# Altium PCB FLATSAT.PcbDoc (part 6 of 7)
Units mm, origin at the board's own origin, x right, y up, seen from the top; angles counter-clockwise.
Board outline 430 x 350 mm, 5 copper layers (Top Layer, Internal Plane 1, Internal Plane 2, DELETEME, Bottom Layer); 808 components, 852 nets, 6407 pads, 939 vias.
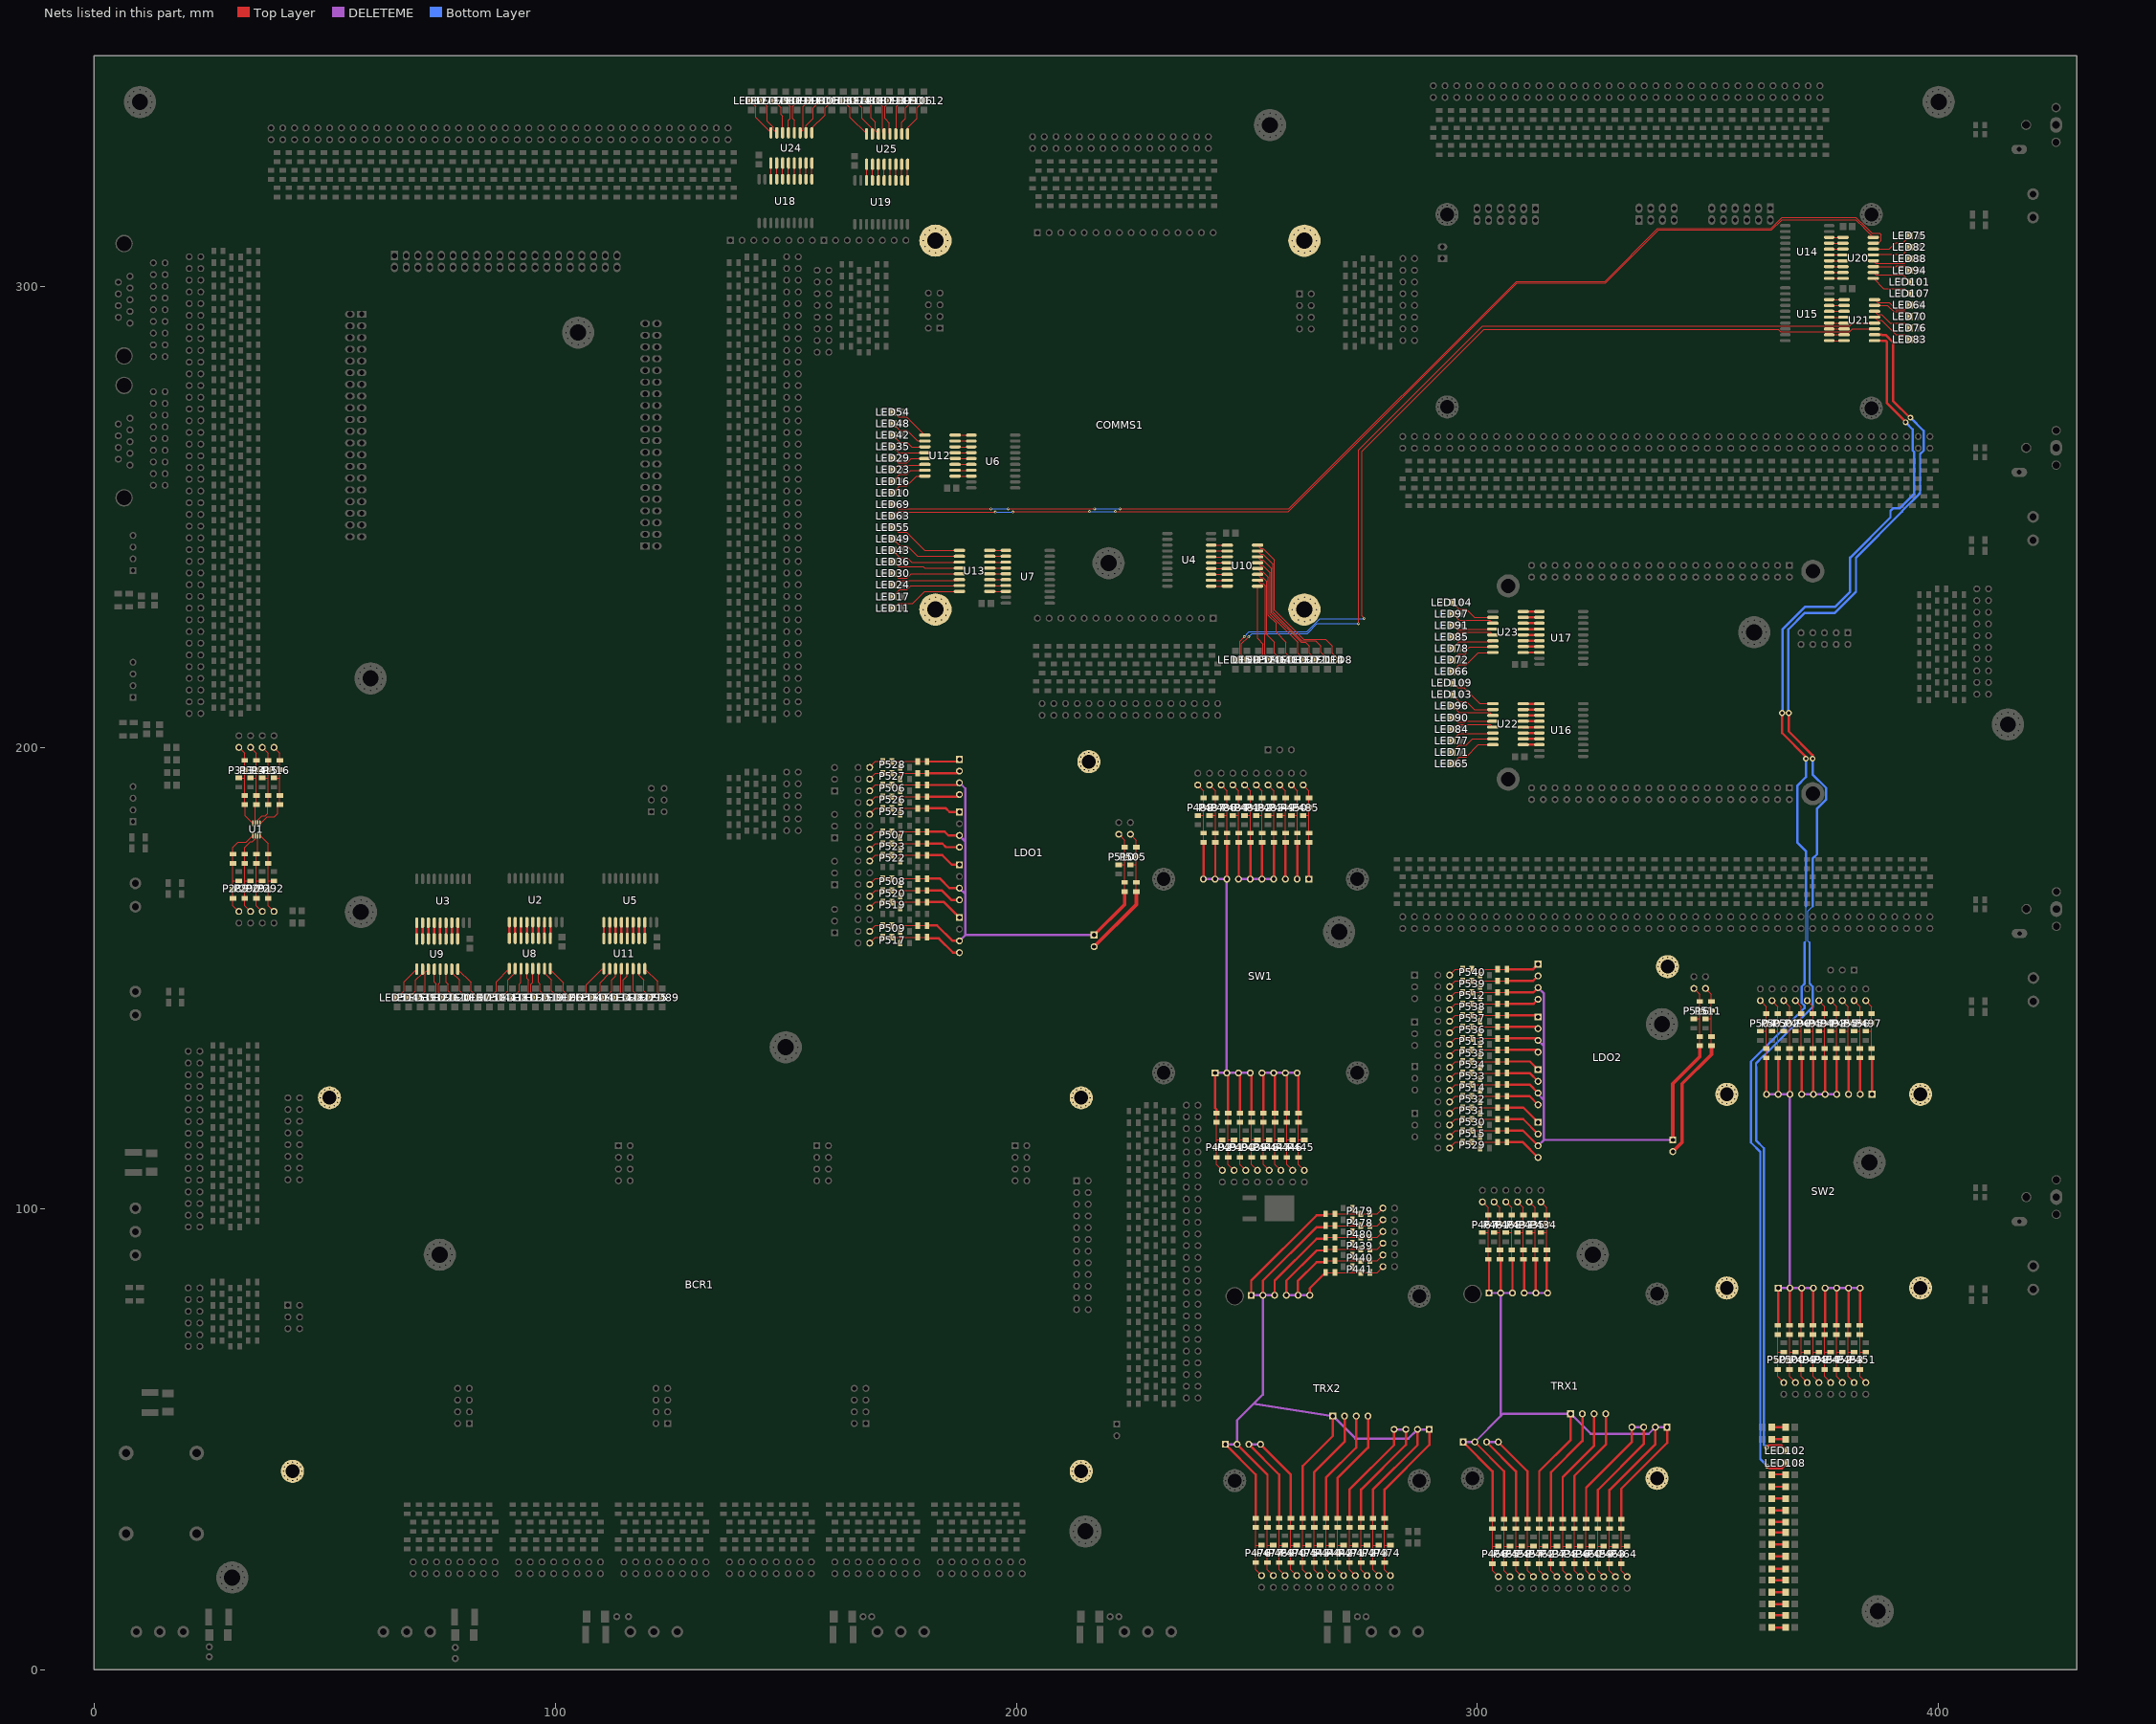
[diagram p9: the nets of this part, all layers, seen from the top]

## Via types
v1: diameter 1.016, hole 0.508, Top Layer to Bottom Layer, 541 vias
v2: diameter 0.6, hole 0.3, Top Layer to Bottom Layer, 214 vias
v3: diameter 1.27, hole 0.711, Top Layer to Bottom Layer, 147 vias
v4: diameter 0.8, hole 0.5, Top Layer to Bottom Layer, 31 vias
v5: diameter 0.5, hole 0.3, Top Layer to Bottom Layer, tented bottom, 5 vias
v6: diameter 1.27, hole 0.635, Top Layer to Bottom Layer, tented both sides, 1 vias

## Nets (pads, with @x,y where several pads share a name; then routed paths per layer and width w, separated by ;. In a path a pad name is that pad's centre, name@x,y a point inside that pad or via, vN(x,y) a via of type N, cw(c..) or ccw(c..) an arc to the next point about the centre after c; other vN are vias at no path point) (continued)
NetLDO1_EN4: LDO1.EN4 P527.2 | length 7.2
  Top Layer w0.508: P527.2@180.658,194.42 180.674,194.42 187.195,194.42 LDO1.EN4@187.671,194.896
NetLDO1_GND: LDO1.GND P506.2 P507.2 P508.2 P509.2 P510.2 | length 109.8
  Top Layer w0.508: P509.2@180.658,161.4 180.674,161.4 182.833,161.4 186.167,158.066 LDO1.GND@187.671,158.066 ; P508.2@180.658,171.56 180.674,171.56 183.468,171.56 185.532,169.496 LDO1.GND@187.671,169.496 ; P507.2@180.658,181.72 180.674,181.72 184.484,181.72 185.278,180.926 LDO1.GND@187.671,180.926 ; P506.2@180.658,191.88 180.674,191.88 187.195,191.88 LDO1.GND@187.671,192.356
  Top Layer w0.762: LDO1.GND@216.881,159.336 223.489,165.944 223.489,168.75 P510.2@223.489,168.766
  DELETEME w0.508: LDO1.GND@187.671,158.066 188.941,159.336 ; LDO1.GND@187.671,169.496 188.941,168.226 ; LDO1.GND@187.671,180.926 188.925,179.672 188.941,179.672 ; LDO1.GND@187.671,192.356 188.941,191.086 188.941,179.672 ; LDO1.GND@216.881,159.336 188.941,159.336 ; 188.941,159.336 188.941,168.226 ; 188.941,168.226 188.941,179.672
NetLDO1_RST1: LDO1.RST1 P519.2 | length 8.4
  Top Layer w0.508: P519.2@180.658,166.48 180.674,166.48 184.337,166.48 LDO1.RST1@187.671,163.146
NetLDO1_RST2: LDO1.RST2 P522.2 | length 7.9
  Top Layer w0.508: P522.2@180.658,176.64 180.674,176.64 183.976,176.64 186.04,174.576 LDO1.RST2@187.671,174.576
NetLDO1_RST3: LDO1.RST3 P525.2 | length 7.3
  Top Layer w0.508: P525.2@180.658,186.8 180.674,186.8 184.738,186.8 185.532,186.006 LDO1.RST3@187.671,186.006
NetLDO1_RST4: LDO1.RST4 P528.2 | length 6.5
  Top Layer w0.508: P528.2@180.658,196.96 180.674,196.96 LDO1.RST4@187.195,196.96
NetLDO1_VIN: LDO1.VIN P505.2 | length 15.9
  Top Layer w0.762: LDO1.VIN@216.881,156.796 226.029,165.944 226.029,168.75 P505.2@226.029,168.766 P505.2@226.029,168.918
NetLDO1_VOUT1: LDO1.VOUT1 P517.2 | length 8.4
  Top Layer w0.508: P517.2@180.658,158.86 180.912,158.606 183.214,158.606 186.294,155.526 LDO1.VOUT1@187.671,155.526
NetLDO1_VOUT2: LDO1.VOUT2 P520.2 | length 7.9
  Top Layer w0.508: P520.2@180.658,169.02 180.674,169.02 183.849,169.02 185.913,166.956 LDO1.VOUT2@187.671,166.956
NetLDO1_VOUT3: LDO1.VOUT3 P523.2 | length 7.3
  Top Layer w0.508: P523.2@180.658,179.18 180.674,179.18 183.976,179.18 184.77,178.386 LDO1.VOUT3@187.671,178.386
NetLDO1_VOUT4: LDO1.VOUT4 P526.2 | length 7.2
  Top Layer w0.508: P526.2@180.658,189.34 180.674,189.34 187.195,189.34 LDO1.VOUT4@187.671,189.816
NetLDO2_EN1: LDO2.EN1 P530.2 | length 8.1
  Top Layer w0.508: P530.2@306.388,119.41 306.404,119.41 309.906,119.41 LDO2.EN1@313.144,116.172
NetLDO2_EN2: LDO2.EN2 P533.2 | length 7.5
  Top Layer w0.508: P533.2@306.388,129.41 306.404,129.41 311.336,129.41 LDO2.EN2@313.144,127.602
NetLDO2_EN3: LDO2.EN3 P536.2 | length 6.9
  Top Layer w0.508: P536.2@306.388,139.41 306.404,139.41 312.766,139.41 LDO2.EN3@313.144,139.032
NetLDO2_EN4: LDO2.EN4 P539.2 | length 7.2
  Top Layer w0.508: P539.2@306.388,149.41 306.404,149.41 312.092,149.41 LDO2.EN4@313.144,150.462
NetLDO2_GND: LDO2.GND P512.2 P513.2 P514.2 P515.2 P516.2 | length 119.7
  Top Layer w0.508: P515.2@306.388,116.91 306.404,116.91 309.866,116.91 LDO2.GND@313.144,113.632 ; P514.2@306.388,126.91 306.404,126.91 311.296,126.91 LDO2.GND@313.144,125.062 ; P513.2@306.388,136.91 306.404,136.91 312.726,136.91 LDO2.GND@313.144,136.492 ; P512.2@306.388,146.91 306.404,146.91 312.132,146.91 LDO2.GND@313.144,147.922
  Top Layer w0.762: LDO2.GND@342.354,114.902 342.354,127.094 348.19,132.93 P516.2@348.19,135.307
  DELETEME w0.508: LDO2.GND@313.144,113.632 314.414,114.902 ; LDO2.GND@313.144,125.062 313.144,124.808 314.414,123.538 ; LDO2.GND@313.144,136.492 314.414,135.222 ; LDO2.GND@313.144,147.922 314.414,146.652 314.414,135.222 ; LDO2.GND@342.354,114.902 314.414,114.902 ; 314.414,114.902 314.414,123.538 ; 314.414,123.538 314.414,135.222
NetLDO2_RST1: LDO2.RST1 P531.2 | length 8.1
  Top Layer w0.508: P531.2@306.388,121.91 306.404,121.91 309.946,121.91 LDO2.RST1@313.144,118.712
NetLDO2_RST2: LDO2.RST2 P534.2 | length 7.5
  Top Layer w0.508: P534.2@306.388,131.91 306.404,131.91 311.376,131.91 LDO2.RST2@313.144,130.142
NetLDO2_RST3: LDO2.RST3 P537.2 | length 6.4
  Top Layer w0.508: P537.2@306.388,141.91 306.404,141.91 LDO2.RST3@312.806,141.91
NetLDO2_RST4: LDO2.RST4 P540.2 | length 7.2
  Top Layer w0.508: P540.2@306.388,151.91 306.404,151.91 312.052,151.91 LDO2.RST4@313.144,153.002
NetLDO2_VIN: LDO2.VIN P511.2 | length 26.4
  Top Layer w0.762: LDO2.VIN@342.354,112.362 344.386,114.394 344.386,127.093 350.73,133.437 P511.2@350.73,135.267
NetLDO2_VOUT1: LDO2.VOUT1 P529.2 | length 8.1
  Top Layer w0.508: P529.2@306.388,114.41 306.404,114.41 309.826,114.41 LDO2.VOUT1@313.144,111.092
NetLDO2_VOUT2: LDO2.VOUT2 P532.2 | length 7.5
  Top Layer w0.508: P532.2@306.388,124.41 306.404,124.41 311.256,124.41 LDO2.VOUT2@313.144,122.522
NetLDO2_VOUT3: LDO2.VOUT3 P535.2 | length 6.9
  Top Layer w0.508: P535.2@306.388,134.41 306.404,134.41 312.686,134.41 LDO2.VOUT3@313.144,133.952
NetLDO2_VOUT4: LDO2.VOUT4 P538.2 | length 7.2
  Top Layer w0.508: P538.2@306.388,144.41 306.404,144.41 312.172,144.41 LDO2.VOUT4@313.144,145.382
NetLED1_1: LED1.1 R12.1 | length 3
  Top Layer w0.508: R12.1@363.803,52.585 LED1.1@366.803,52.585
NetLED2_1: LED2.1 R13.1 | length 3
  Top Layer w0.508: R13.1@363.803,49.965 363.883,49.965 363.903,49.985 366.783,49.985 LED2.1@366.803,49.965
NetLED3_1: LED3.1 R14.1 | length 3.1
  Top Layer w0.508: R14.1@363.803,42.265 363.983,42.265 364.103,42.385 366.683,42.385 LED3.1@366.803,42.265
NetLED4_1: LED4.1 R15.1 | length 3
  Top Layer w0.508: R15.1@363.803,39.685 LED4.1@366.803,39.685
NetLED5_1: LED5.1 R16.1 | length 3.5
  Top Layer w0.508: R16.1@363.803,37.105 363.803,36.885 364.003,36.685 364.423,37.105 LED5.1@366.803,37.105
NetLED6_2: LED6.2 U8.16 | length 8.1
  Top Layer w0.152: U8.16@98.965,152.05 98.965,151.809 101.754,149.02 101.754,147.246 LED6.2@103.25,145.75
NetLED7_2: LED7.2 U9.16 | length 8
  Top Layer w0.152: U9.16@78.89,151.925 81.754,149.061 81.754,147.246 LED7.2@83.25,145.75
NetLED8_2: LED8.2 U10.16 | length 35.3
  Top Layer w0.152: U10.16@252.325,243.89 252.991,243.224 253.475,243.224 255.981,240.718 255.981,229.769 262.25,223.5 267.033,223.5 268.504,222.029 268.504,220.496 LED8.2@270,219
NetLED9_2: LED9.2 U21.12 | length 192.1
  Top Layer w0.152: LED9.2@250,219 248.834,220.166 248.834,222.484 250.378,224.028 v2(250.403,224.028) ; v2(274.2,226.875) 274.2,264.54 301.116,291.456 380.65,291.456 381.254,292.06 U21.12@386.075,292.06
  Bottom Layer w0.152: v2(250.403,224.028) 251.128,224.753 263.128,224.753 263.225,224.85 265.25,226.875 v2(274.2,226.875)
NetLED10_2: LED10.2 U12.16 | length 8.4
  Top Layer w0.152: LED10.2@173.25,255.25 174.746,256.746 176.279,256.746 178.393,258.86 U12.16@180.175,258.86
NetLED11_2: LED11.2 U13.16 | length 15.9
  Top Layer w0.152: LED11.2@173.25,230.25 173.441,230.25 174.445,231.254 177.569,231.254 180.175,233.86 U13.16@187.675,233.86
NetLED12_2: LED12.2 U8.15 | length 7.6
  Top Layer w0.152: U8.15@97.695,152.05 97.695,151.113 99.254,149.554 99.254,147.246 LED12.2@100.75,145.75
NetLED13_2: LED13.2 U9.15 | length 7.5
  Top Layer w0.152: U9.15@77.62,151.925 77.62,151.188 79.254,149.554 79.254,147.246 LED13.2@80.75,145.75
NetLED14_2: LED14.2 U10.15 | length 32
  Top Layer w0.152: U10.15@252.325,242.62 252.991,241.954 253.475,241.954 255.651,239.778 255.651,229.349 261.866,223.134 264.899,223.134 266.004,222.029 266.004,220.687 267.5,219.191 LED14.2@267.5,219
NetLED15_2: LED15.2 U21.11 | length 192.5
  Top Layer w0.152: LED15.2@247.5,219 247.5,219.042 248.504,220.046 248.504,223.054 249.428,223.978 v2(249.428,224.028) ; v2(275.45,228) 274.925,228.525 274.925,264.2 301.445,290.72 365.166,290.72 365.7,290.186 380.65,290.186 381.254,290.79 U21.11@386.075,290.79
  Bottom Layer w0.152: v2(249.428,224.028) 250.483,225.083 262.992,225.083 265.833,227.925 275.375,227.925 v2(275.45,228)
NetLED16_2: LED16.2 U12.15 | length 7.9
  Top Layer w0.152: LED16.2@173.25,257.75 174.746,259.246 176.279,259.246 177.163,260.13 U12.15@180.175,260.13
NetLED17_2: LED17.2 U13.15 | length 15.4
  Top Layer w0.152: LED17.2@173.25,232.75 174.746,234.246 176.279,234.246 177.163,235.13 U13.15@187.675,235.13
NetLED18_1: LED18.1 R17.1 | length 3
  Top Layer w0.508: R17.1@363.803,34.525 LED18.1@366.803,34.525
NetLED19_2: LED19.2 U8.14 | length 7.1
  Top Layer w0.152: U8.14@96.425,152.05 96.425,149.033 96.754,148.704 96.754,147.246 LED19.2@98.25,145.75
NetLED20_2: LED20.2 U9.14 | length 7
  Top Layer w0.152: U9.14@76.35,151.925 76.35,149.108 76.754,148.704 76.754,147.246 LED20.2@78.25,145.75
NetLED21_2: LED21.2 U10.14 | length 28.5
  Top Layer w0.152: U10.14@252.325,241.35 252.991,240.684 253.475,240.684 255.321,238.838 255.321,229.212 261.729,222.804 262.729,222.804 263.504,222.029 263.504,220.496 LED21.2@265,219
NetLED22_2: LED22.2 U11.14 | length 6.8
  Top Layer w0.152: U11.14@116.923,152.025 116.923,147.077 LED22.2@118.25,145.75
NetLED23_2: LED23.2 U12.14 | length 7.4
  Top Layer w0.152: LED23.2@173.25,260.25 173.441,260.25 174.445,261.254 180.029,261.254 U12.14@180.175,261.4
NetLED24_2: LED24.2 U13.14 | length 14.9
  Top Layer w0.152: LED24.2@173.25,235.25 173.441,235.25 174.445,236.254 187.529,236.254 U13.14@187.675,236.4
NetLED25_2: LED25.2 U8.13 | length 6.9
  Top Layer w0.152: U8.13@95.155,152.05 95.155,149.113 94.746,148.704 94.746,146.945 95.75,145.941 LED25.2@95.75,145.75
NetLED26_2: LED26.2 U9.13 | length 6.7
  Top Layer w0.152: U9.13@75.08,151.925 75.08,149.038 74.746,148.704 74.746,146.945 75.75,145.941 LED26.2@75.75,145.75
NetLED27_2: LED27.2 U10.13 | length 25.6
  Top Layer w0.152: U10.13@252.325,240.08 252.991,239.414 253.475,239.414 254.991,237.899 254.991,228.817 261.004,222.804 261.004,220.496 LED27.2@262.5,219
NetLED28_2: LED28.2 U11.13 | length 7.1
  Top Layer w0.152: U11.13@115.653,152.025 115.653,150.461 114.746,149.554 114.746,146.945 115.75,145.941 LED28.2@115.75,145.75
NetLED29_2: LED29.2 U12.13 | length 7.7
  Top Layer w0.152: LED29.2@173.25,262.75 173.441,262.75 174.445,261.746 176.279,261.746 177.203,262.67 U12.13@180.175,262.67
NetLED30_2: LED30.2 U13.13 | length 15.2
  Top Layer w0.152: LED30.2@173.25,237.75 173.441,237.75 174.445,236.746 176.279,236.746 177.203,237.67 U13.13@187.675,237.67
NetLED31_2: LED31.2 U8.12 | length 6.9
  Top Layer w0.152: LED31.2@93.25,145.75 93.25,145.941 94.254,146.945 94.254,149.554 93.885,149.923 U8.12@93.885,152.05
NetLED32_2: LED32.2 U9.12 | length 6.8
  Top Layer w0.152: LED32.2@73.25,145.75 73.25,145.941 74.254,146.945 74.254,148.704 73.81,149.148 U9.12@73.81,151.925
NetLED33_2: LED33.2 U10.12 | length 23.3
  Top Layer w0.152: U10.12@252.325,238.81 252.991,238.144 253.475,238.144 254.66,236.959 254.66,228.681 256.334,227.007 256.334,224.974 258.504,222.804 258.504,220.496 LED33.2@260,219
NetLED34_2: LED34.2 U11.12 | length 6.7
  Top Layer w0.152: LED34.2@113.25,145.75 113.25,145.941 114.254,146.945 114.254,151.896 U11.12@114.383,152.025
NetLED35_2: LED35.2 U12.12 | length 7.5
  Top Layer w0.152: LED35.2@173.25,265.25 174.56,263.94 U12.12@180.175,263.94
NetLED36_2: LED36.2 U13.12 | length 15.4
  Top Layer w0.152: LED36.2@173.25,240.25 173.441,240.25 174.445,239.246 179.869,239.246 180.175,238.94 U13.12@187.675,238.94 U13.12@187.369,239.246
NetLED37_1: LED37.1 R18.1 | length 3.6
  Top Layer w0.508: R18.1@363.803,32.025 363.803,31.585 364.243,32.025 LED37.1@366.803,32.025
NetLED38_2: LED38.2 U8.11 | length 7.1
  Top Layer w0.152: LED38.2@90.75,145.75 92.246,147.246 92.246,148.704 92.615,149.073 U8.11@92.615,152.05
NetLED39_2: LED39.2 U9.11 | length 6.9
  Top Layer w0.152: LED39.2@70.75,145.75 70.75,145.941 71.874,147.065 71.874,151.259 U9.11@72.54,151.925
NetLED40_2: LED40.2 U10.11 | length 21
  Top Layer w0.152: U10.11@252.325,237.54 252.991,236.874 253.475,236.874 254.33,236.019 254.33,224.478 256.004,222.804 256.004,220.496 LED40.2@257.5,219
NetLED41_2: LED41.2 U11.11 | length 7.3
  Top Layer w0.152: LED41.2@110.75,145.75 112.246,147.246 112.246,149.554 113.113,150.421 U11.11@113.113,152.025
NetLED42_2: LED42.2 U12.11 | length 8
  Top Layer w0.152: LED42.2@173.25,267.75 174.746,266.254 176.279,266.254 177.323,265.21 U12.11@180.175,265.21
NetLED43_2: LED43.2 U13.11 | length 15.5
  Top Layer w0.152: LED43.2@173.25,242.75 174.746,241.254 176.279,241.254 177.323,240.21 U13.11@187.675,240.21
NetLED44_2: LED44.2 U8.10 | length 7.6
  Top Layer w0.152: LED44.2@88.25,145.75 89.746,147.246 89.746,149.554 91.345,151.153 U8.10@91.345,152.05
NetLED45_2: LED45.2 U9.10 | length 7.4
  Top Layer w0.152: LED45.2@68.25,145.75 69.746,147.246 69.746,149.554 71.27,151.078 U9.10@71.27,151.925
NetLED46_2: LED46.2 U10.10 | length 18.8
  Top Layer w0.152: U10.10@252.325,236.27 252.991,235.604 253.475,235.604 254,235.079 254,224.641 253.85,224.491 253.85,220.15 LED46.2@255,219
NetLED47_2: LED47.2 U11.10 | length 7.8
  Top Layer w0.152: LED47.2@108.25,145.75 109.746,147.246 109.746,149.014 111.843,151.111 U11.10@111.843,152.025
NetLED48_2: LED48.2 U12.10 | length 8.5
  Top Layer w0.152: LED48.2@173.25,270.25 174.746,268.754 176.279,268.754 178.553,266.48 U12.10@180.175,266.48
NetLED49_2: LED49.2 U13.10 | length 16
  Top Layer w0.152: LED49.2@173.25,245.25 174.746,243.754 176.279,243.754 178.553,241.48 U13.10@187.675,241.48
NetLED50_2: LED50.2 U8.9 | length 8.1
  Top Layer w0.152: LED50.2@85.75,145.75 87.246,147.246 87.246,149.221 U8.9@90.075,152.05
NetLED51_2: LED51.2 U9.9 | length 7.9
  Top Layer w0.152: LED51.2@65.75,145.75 67.246,147.246 67.246,149.171 U9.9@70,151.925
NetLED52_2: LED52.2 U10.9 | length 16.9
  Top Layer w0.152: U10.9@252.325,235 252.325,223.633 253.52,222.438 253.52,220.211 252.5,219.191 LED52.2@252.5,219
NetLED53_2: LED53.2 U11.9 | length 8.4
  Top Layer w0.152: LED53.2@105.75,145.75 105.75,145.941 106.754,146.945 106.754,148.537 110.242,152.025 U11.9@110.492,152.025
NetLED54_2: LED54.2 U12.9 | length 9
  Top Layer w0.152: LED54.2@173.25,272.75 173.441,272.75 174.445,271.746 176.179,271.746 U12.9@180.175,267.75
NetLED55_2: LED55.2 U13.9 | length 16.5
  Top Layer w0.152: LED55.2@173.25,247.75 173.441,247.75 174.445,246.746 176.179,246.746 180.175,242.75 U13.9@187.675,242.75
NetLED56_1: LED56.1 R19.1 | length 3
  Top Layer w0.508: R19.1@363.803,29.765 LED56.1@366.803,29.765
NetLED57_1: LED57.1 R20.1 | length 3
  Top Layer w0.508: R20.1@363.803,27.185 LED57.1@366.803,27.185
NetLED58_1: LED58.1 R21.1 | length 3
  Top Layer w0.508: R21.1@363.803,24.605 LED58.1@366.803,24.605
NetLED59_1: LED59.1 R22.1 | length 3.4
  Top Layer w0.508: R22.1@363.803,21.865 363.803,21.685 364.003,21.485 364.383,21.865 LED59.1@366.803,21.865
NetLED60_1: LED60.1 R23.1 | length 3.1
  Top Layer w0.508: R23.1@363.803,19.445 363.803,19.385 363.863,19.445 LED60.1@366.803,19.445
NetLED61_1: LED61.1 R24.1 | length 3
  Top Layer w0.508: R24.1@363.803,11.785 LED61.1@366.803,11.785
NetLED62_1: LED62.1 R25.1 | length 3.6
  Top Layer w0.508: R25.1@363.803,16.825 363.803,16.485 363.903,16.385 364.343,16.825 LED62.1@366.803,16.825
NetLED63_2: LED63.2 U20.16 | length 241
  Top Layer w0.152: LED63.2@173.25,250.25 173.441,250.25 174.445,251.254 176.055,251.254 ; 176.059,251.25 176.055,251.254 ; v2(195.453,251.079) 176.23,251.079 176.055,251.254 ; v2(199.263,251.079) 199.39,251.206 v2(215.9,251.206) ; v2(221.488,251.206) 222.261,251.206 ; 222.271,251.196 258.988,251.196 308.579,300.787 327.787,300.787 339.25,312.25 363.75,312.25 366,314.5 382,314.5 383.75,312.75 383.75,312.715 U20.16@385.825,310.64
  Bottom Layer w0.152: v2(195.453,251.079) v2(199.263,251.079) ; v2(215.9,251.206) 216.154,251.206 216.164,251.196 221.478,251.196 v2(221.488,251.206)
NetLED64_2: LED64.2 U21.16 | length 9.2
  Top Layer w0.152: U21.16@386.211,297.004 U21.16@386.075,297.14 386.741,296.474 389.243,296.474 390.721,294.996 392.555,294.996 393.559,296 LED64.2@393.75,296
NetLED65_2: LED65.2 U22.16 | length 10.5
  Top Layer w0.152: LED65.2@294.5,196.5 295.996,197.996 297.529,197.996 300.143,200.61 U22.16@303.346,200.61
NetLED66_2: LED66.2 U23.16 | length 10.5
  Top Layer w0.152: LED66.2@294.5,216.5 295.996,217.996 297.529,217.996 300.143,220.61 U23.16@303.346,220.61
NetLED67_2: LED67.2 U24.16 | length 8.7
  Top Layer w0.152: LED67.2@142.5,340.25 142.5,340.059 143.504,339.055 143.504,336.611 U24.16@146.79,333.325
NetLED68_2: LED68.2 U25.16 | length 9.3
  Top Layer w0.152: LED68.2@162.5,340.25 163.996,338.754 163.996,336.619 U25.16@167.54,333.075
NetLED69_2: LED69.2 U20.15 | length 245.7
  Top Layer w0.152: LED69.2@173.25,252.75 173.441,252.75 174.445,251.746 176.055,251.746 ; 176.059,251.75 176.055,251.746 ; v2@194.5,251.746 176.055,251.746 ; v2(198.25,251.75) 198.304,251.804 198.358,251.75 215.661,251.75 215.671,251.76 216.99,251.76 v2(217,251.75) ; v2(222.5,251.75) 259.075,251.75 308.442,301.117 327.617,301.117 339.08,312.58 363.613,312.58 366.033,315 382,315 384.25,312.75 ; 384.25,312.75 385.5,311.5 387.25,311.5 387.5,311.25 387.5,310 386.87,309.37 U20.15@385.825,309.37
  Bottom Layer w0.152: v2(194.5,251.75) 194.554,251.804 194.608,251.75 v2(198.25,251.75) ; v2(217,251.75) 217.01,251.76 222.49,251.76 v2(222.5,251.75)
NetLED70_2: LED70.2 U21.15 | length 8.7
  Top Layer w0.152: U21.15@386.075,295.87 388.914,295.87 390.28,294.504 392.746,294.504 LED70.2@393.75,293.5
NetLED71_2: LED71.2 U22.15 | length 10
  Top Layer w0.152: LED71.2@294.5,199 295.996,200.496 297.529,200.496 298.913,201.88 U22.15@303.346,201.88
NetLED72_2: LED72.2 U23.15 | length 10.4
  Top Layer w0.152: LED72.2@294.5,219 295.8,220.3 297.325,220.3 297.7,220.675 297.7,221.3 298.246,221.846 303.312,221.846 U23.15@303.346,221.88
NetLED73_2: LED73.2 U24.15 | length 8.2
  Top Layer w0.152: LED73.2@145,340.25 145,340.059 146.004,339.055 146.004,335.865 147.394,334.475 147.394,333.991 U24.15@148.06,333.325
NetLED74_2: LED74.2 U25.15 | length 8.8
  Top Layer w0.152: LED74.2@165,340.25 166.496,338.754 166.496,336.446 168.81,334.132 U25.15@168.81,333.075
NetLED75_2: LED75.2 U20.14 | length 9.1
  Top Layer w0.152: U20.14@385.825,308.1 389.317,308.1 390.721,309.504 392.254,309.504 LED75.2@393.75,311
NetLED76_2: LED76.2 U21.14 | length 9.2
  Top Layer w0.152: U21.14@386.075,294.6 386.741,293.934 387.579,293.934 389.509,292.004 392.555,292.004 393.559,291 LED76.2@393.75,291
NetLED77_2: LED77.2 U22.14 | length 9.5
  Top Layer w0.152: LED77.2@294.5,201.5 295.996,202.996 303.192,202.996 U22.14@303.346,203.15
NetLED78_2: LED78.2 U23.14 | length 9.5
  Top Layer w0.152: LED78.2@294.5,221.5 295.996,222.996 303.192,222.996 U23.14@303.346,223.15
NetLED79_2: LED79.2 U24.14 | length 7.7
  Top Layer w0.152: LED79.2@147.5,340.25 148.996,338.754 148.996,337.296 149.33,336.962 U24.14@149.33,333.325
NetLED80_2: LED80.2 U25.14 | length 8.2
  Top Layer w0.152: LED80.2@167.5,340.25 167.5,340.208 168.504,339.204 168.504,336.545 169.414,335.635 169.414,333.741 U25.14@170.08,333.075
NetLED81_1: LED81.1 R26.1 | length 3.2
  Top Layer w0.508: R26.1@363.803,9.165 366.123,9.165 366.403,8.885 366.523,8.885 LED81.1@366.803,9.165
NetLED82_2: LED82.2 U20.13 | length 8.6
  Top Layer w0.152: U20.13@385.825,306.83 385.999,307.004 392.254,307.004 LED82.2@393.75,308.5
NetLED83_2: LED83.2 U21.13 | length 9.7
  Top Layer w0.152: U21.13@386.075,293.33 386.741,292.664 387.579,292.664 390.739,289.504 392.555,289.504 393.559,288.5 LED83.2@393.75,288.5
NetLED84_2: LED84.2 U22.13 | length 9.5
  Top Layer w0.152: LED84.2@294.5,204 294.691,204 295.695,205.004 302.762,205.004 U22.13@303.346,204.42
NetLED85_2: LED85.2 U23.13 | length 9.5
  Top Layer w0.152: LED85.2@294.5,224 294.691,224 295.695,225.004 302.762,225.004 U23.13@303.346,224.42
NetLED86_2: LED86.2 U24.13 | length 7.5
  Top Layer w0.152: LED86.2@150,340.25 150,340.059 151.004,339.055 151.004,336.446 150.6,336.042 U24.13@150.6,333.325
NetLED87_2: LED87.2 U25.13 | length 7.7
  Top Layer w0.152: LED87.2@170,340.25 170,340.059 171.004,339.055 171.004,333.421 U25.13@171.35,333.075
NetLED88_2: LED88.2 U20.12 | length 8.6
  Top Layer w0.152: U20.12@385.825,305.56 386.389,304.996 392.555,304.996 393.559,306 LED88.2@393.75,306
NetLED89_2: LED89.2 U11.16 | length 7.8
  Top Layer w0.152: U11.16@119.463,152.025 122.246,149.242 122.246,146.945 123.25,145.941 LED89.2@123.25,145.75
NetLED90_2: LED90.2 U22.12 | length 9.3
  Top Layer w0.152: LED90.2@294.5,206.5 294.691,206.5 295.695,205.496 297.305,205.496 297.499,205.69 U22.12@303.346,205.69
NetLED91_2: LED91.2 U23.12 | length 9.3
  Top Layer w0.152: LED91.2@294.5,226.5 294.691,226.5 295.695,225.496 297.305,225.496 297.499,225.69 U23.12@303.346,225.69
NetLED92_2: LED92.2 U24.12 | length 7.5
  Top Layer w0.152: U24.12@151.87,333.325 151.87,336.072 151.496,336.446 151.496,339.055 152.5,340.059 LED92.2@152.5,340.25
NetLED93_2: LED93.2 U25.12 | length 8.1
  Top Layer w0.152: LED93.2@172.5,340.25 172.5,340.059 171.496,339.055 171.496,336.446 172.5,335.442 172.5,333.195 U25.12@172.62,333.075
NetLED94_2: LED94.2 U20.11 | length 8.4
  Top Layer w0.152: U20.11@385.825,304.29 390.731,304.29 390.945,304.504 392.555,304.504 393.559,303.5 LED94.2@393.75,303.5
NetLED95_2: LED95.2 U11.15 | length 7.3
  Top Layer w0.152: U11.15@118.193,152.025 118.193,150.615 119.254,149.554 119.254,147.246 LED95.2@120.75,145.75
NetLED96_2: LED96.2 U22.11 | length 9.7
  Top Layer w0.152: LED96.2@294.5,209 294.691,209 296.065,207.626 302.68,207.626 U22.11@303.346,206.96
NetLED97_2: LED97.2 U23.11 | length 9.7
  Top Layer w0.152: LED97.2@294.5,229 294.691,229 296.065,227.626 302.68,227.626 U23.11@303.346,226.96
NetLED98_2: LED98.2 U24.11 | length 7.7
  Top Layer w0.152: U24.11@153.14,333.325 153.806,333.991 153.806,339.014 155,340.208 LED98.2@155,340.25
NetLED99_2: LED99.2 U25.11 | length 7.6
  Top Layer w0.152: U25.11@173.89,333.075 173.996,333.181 173.996,339.055 175,340.059 LED99.2@175,340.25
NetLED100_1: LED100.1 R27.1 | length 3
  Top Layer w0.508: R27.1@363.803,14.245 LED100.1@366.803,14.245
NetLED101_2: LED101.2 U20.10 | length 8.8
  Top Layer w0.152: U20.10@385.825,303.02 386.349,302.496 392.254,302.496 LED101.2@393.75,301
NetLED102_2: LED102.2 U21.10 | length 279.9
  Top Layer w0.508: v1(362.703,48.185) 363.165,48.647 365.941,48.647 366.808,47.78 LED102.2@366.808,47.465 ; v3(367.492,207.485) 367.492,203.496 372.651,198.337 v3(372.651,197.585) ; U21.10@386.075,289.52 387.643,289.52 387.708,289.455 388.603,289.455 388.603,289.362 390.073,287.892 390.073,275.215 393.74,271.548 v3(393.866,271.548)
  Bottom Layer w0.203: 372.003,157.685 371.645,158.043 371.645,164.579 372.651,165.585
  Bottom Layer w0.508: v1(362.703,48.185) 362.103,48.785 362.103,113.085 360.403,114.785 360.403,130.734 360.384,130.753 360.384,131.532 361.96,133.107 362.081,133.107 372.666,143.692 372.666,148.142 372.003,148.805 372.003,157.685 ; v3(367.492,207.485) 367.403,207.574 367.403,225.615 371.003,229.215 377.503,229.215 382.073,233.785 382.073,241.185 392.078,251.19 392.078,251.324 395.839,255.085 395.973,255.085 395.973,263.649 396.74,264.415 396.74,268.674 v3(393.866,271.548) ; 372.651,165.585 372.651,175.899 373.638,176.886 373.638,186.769 375.63,188.761 375.63,191.189 372.651,194.168 v3(372.651,197.585)
NetLED103_2: LED103.2 U22.10 | length 10.2
  Top Layer w0.152: LED103.2@294.5,211.5 295.996,210.004 297.529,210.004 299.303,208.23 U22.10@303.346,208.23
NetLED104_2: LED104.2 U23.10 | length 10.2
  Top Layer w0.152: LED104.2@294.5,231.5 295.996,230.004 297.529,230.004 299.303,228.23 U23.10@303.346,228.23
NetLED105_2: LED105.2 U24.10 | length 8.2
  Top Layer w0.152: U24.10@154.41,333.325 154.41,334.852 156.004,336.446 156.004,338.754 LED105.2@157.5,340.25
NetLED106_2: LED106.2 U25.10 | length 8.1
  Top Layer w0.152: U25.10@175.16,333.075 175.16,335.602 176.004,336.446 176.004,338.754 LED106.2@177.5,340.25
NetLED107_2: LED107.2 U20.9 | length 9.3
  Top Layer w0.152: U20.9@385.825,301.75 388.071,299.504 392.555,299.504 393.559,298.5 LED107.2@393.75,298.5
NetLED108_2: LED108.2 U21.9 | length 281.3
  Top Layer w0.508: v1(362.803,44.185) 363.305,43.683 366.001,43.683 366.808,44.49 LED108.2@366.808,44.865 ; v3(366.044,207.485) 366.044,203.148 371.203,197.989 v3(371.203,197.585) ; U21.9@386.075,288.25 387.643,288.25 387.708,288.185 388.603,288.185 388.803,287.985 388.803,274.689 392.842,270.65 v3(392.842,270.524)
  Bottom Layer w0.203: 370.903,157.685 371.213,157.995 371.213,165.575
  Bottom Layer w0.254: 371.203,165.585 371.213,165.575
  Bottom Layer w0.508: v1@363.003,44.185 v1(362.803,44.185) 361.325,45.663 361.325,112.307 359.303,114.329 359.303,131.885 370.903,143.485 370.903,144.022 370.302,144.623 370.302,148.142 370.903,148.742 370.903,157.685 ; v3(366.044,207.485) 366.133,207.574 366.133,225.615 371.003,230.485 377.503,230.485 380.803,233.785 380.803,241.185 389.538,249.92 389.538,251.324 390.089,251.875 391.493,251.875 394.703,255.085 394.703,264.089 394.376,264.415 394.376,268.99 v3(392.842,270.524) ; 371.203,165.585 371.203,177.559 369.318,179.444 369.318,191.708 371.203,193.593 v3(371.203,197.585)
NetLED109_2: LED109.2 U22.9 | length 10.8
  Top Layer w0.152: LED109.2@294.5,214 294.691,214 295.695,212.996 297.037,212.996 300.425,209.608 303.238,209.608 U22.9@303.346,209.5 U22.9@303.346,209.608
NetLED111_2: LED111.2 U24.9 | length 8.7
  Top Layer w0.152: U24.9@155.68,333.325 155.68,334.397 158.504,337.221 158.504,338.754 LED111.2@160,340.25
NetLED112_2: LED112.2 U25.9 | length 8.7
  Top Layer w0.152: U25.9@176.43,333.075 176.43,334.372 178.504,336.446 178.504,338.754 LED112.2@180,340.25
NetP289_2: P289.2 U1.1 | length 6.8
  Top Layer w0.254: P289.2@30.169,176.906 30.169,178.346 31.256,179.432 33.016,179.432 U1.1@34.499,180.915
NetP290_2: P290.2 U1.2 | length 5.2
  Top Layer w0.254: P290.2@32.709,176.89 32.709,176.906 32.709,178.346 33.967,179.604 34.368,179.604 34.979,180.215 34.979,180.896 U1.2@34.999,180.915
NetP291_2: P291.2 U1.3 | length 3.9
  Top Layer w0.254: P291.2@35.499,177.06 U1.3@35.499,180.915
NetP292_2: P292.2 U1.4 | length 4.8
  Top Layer w0.254: U1.4@35.999,180.915 37.789,179.125 P292.2@37.789,176.906
NetP313_2: P313.2 U1.8 | length 4.8
  Top Layer w0.254: P313.2@32.709,187.59 32.844,187.456 32.844,185.221 U1.8@34.499,183.565
NetP314_2: P314.2 U1.7 | length 3.8
  Top Layer w0.254: U1.7@34.999,183.565 P314.2@34.999,187.324
NetP315_2: P315.2 U1.6 | length 5.4
  Top Layer w0.254: U1.6@35.499,183.565 35.519,183.585 35.519,184.239 36.472,185.192 37.162,185.192 37.67,185.7 37.67,187.455 P315.2@37.789,187.574
NetP316_2: P316.2 U1.5 | length 6.2
  Top Layer w0.254: U1.5@35.999,183.565 36.182,183.565 37.555,184.938 39.132,184.938 39.897,185.703 P316.2@39.897,187.159
NetP433_2: P433.2 P434.2 P435.2 TRX1.1 | length 26.5
  Top Layer w0.508: TRX1.1@310.12,81.698 P433.2@310.12,88.85 ; TRX1.1@312.66,81.698 P435.2@312.66,88.85 ; TRX1.1@315.04,81.858 315.04,88.994 P434.2@315.04,89.01
  DELETEME w0.508: TRX1.1@310.12,81.698 TRX1.1@312.66,81.698 TRX1.1@315.2,81.698
NetP436_2: P436.2 TRX1.7 | length 25.7
  Top Layer w0.508: P436.2@321.017,32.626 321.017,42.04 327.824,48.847 TRX1.7@327.824,55.511
NetP437_2: P437.2 TRX1.3 | length 25.7
  Top Layer w0.508: P437.2@315.937,32.626 315.937,42.802 322.744,49.609 TRX1.3@322.744,55.511
NetP438_2: P438.2 TRX1.4 | length 25.7
  Top Layer w0.508: P438.2@318.477,32.61 318.477,32.626 318.477,41.786 325.284,48.593 TRX1.4@325.284,55.511
NetP439_2: P439.2 P440.2 P441.2 TRX2.1 | length 36.9
  Top Layer w0.508: TRX2.1@258.558,81.206 258.558,84.362 265.124,90.928 266.759,90.928 P439.2@267.064,91.233 ; TRX2.1@261.098,81.206 261.098,84.362 265.124,88.388 266.759,88.388 P440.2@267.064,88.693 ; TRX2.1@263.638,81.206 263.638,82.727 P441.2@267.064,86.153
  DELETEME w0.508: TRX2.1@258.558,81.206 TRX2.1@261.098,81.206 TRX2.1@263.638,81.206
NetP442_2: P442.2 TRX2.7 | length 24.9
  Top Layer w0.508: P442.2@269.701,32.844 269.701,32.86 269.701,41.623 276.262,48.184 TRX2.7@276.262,55.019
NetP443_2: P443.2 TRX2.3 | length 24.9
  Top Layer w0.508: P443.2@264.621,32.844 264.621,32.86 264.621,42.893 271.182,49.454 TRX2.3@271.182,55.019
NetP444_2: P444.2 TRX2.4 | length 24.9
  Top Layer w0.508: P444.2@267.161,32.844 267.161,32.86 267.161,41.623 273.722,48.184 TRX2.4@273.722,55.019
NetP445_2: P445.2 P446.2 P447.2 P448.2 SW1.Vin | length 43
  Top Layer w0.508: SW1.Vin@253.261,129.434 253.572,129.123 253.572,121.519 253.572,120.744 P448.2@253.572,120.728 ; SW1.Vin@255.801,129.434 256.112,129.123 256.112,121.519 256.112,120.744 P447.2@256.112,120.728 ; SW1.Vin@258.341,129.434 258.652,129.123 258.652,121.519 258.652,120.744 P446.2@258.652,120.728 ; SW1.Vin@260.881,129.434 261.192,129.123 261.192,121.519 261.192,120.744 P445.2@261.192,120.728
  DELETEME w0.508: SW1.Vin@253.261,129.434 SW1.Vin@255.801,129.434 SW1.Vin@258.341,129.434 SW1.Vin@260.881,129.434
NetP449_2: P449.2 SW1.EN | length 7.9
  Top Layer w0.508: SW1.EN@258.398,171.516 258.398,179.434 P449.2@258.398,179.45
NetP450_2: P450.2 SW1.SYNC | length 7.9
  Top Layer w0.508: SW1.SYNC@260.938,171.516 260.938,179.434 P450.2@260.938,179.45
NetP451_2: P451.2 P452.2 P453.2 P454.2 SW2.Vin | length 39.6
  Top Layer w0.508: P454.2@375.364,74.776 SW2.Vin@375.364,82.761 ; P452.2@377.904,74.776 SW2.Vin@377.904,82.761 ; P453.2@380.444,74.776 SW2.Vin@380.444,82.761 ; P451.2@382.984,74.776 SW2.Vin@382.984,82.761
  DELETEME w0.508: SW2.Vin@375.364,82.761 SW2.Vin@377.904,82.761 SW2.Vin@380.444,82.761 SW2.Vin@382.984,82.761
NetP455_2: P455.2 SW2.EN | length 7.8
  Top Layer w0.508: SW2.EN@380.444,124.786 P455.2@380.444,132.612
NetP456_2: P456.2 SW2.SYNC | length 7.8
  Top Layer w0.508: SW2.SYNC@382.984,124.786 P456.2@382.984,132.612
NetP457_2: P457.2 P458.2 TRX1.5 | length 41.3
  Top Layer w0.508: TRX1.5@301.967,49.39 308.317,43.04 308.317,32.626 P458.2@308.317,32.61 ; TRX1.5@304.507,49.39 310.857,43.04 P457.2@310.857,32.626
  DELETEME w0.508: TRX1.5@301.967,49.39 TRX1.5@304.507,49.39
NetP459_2: P459.2 P460.2 TRX1.6 | length 50.8
  Top Layer w0.508: P460.2@323.557,32.61 323.557,32.626 323.557,39.5 333.488,49.431 TRX1.6@333.488,52.615 ; P459.2@326.097,32.61 326.097,32.626 326.097,38.992 336.028,48.923 TRX1.6@336.028,52.615
  DELETEME w0.508: TRX1.6@333.488,52.615 TRX1.6@336.028,52.615
NetP461_2: P461.2 P462.2 P463.2 P464.2 P465.2 P466.2 P467.2 P468.2 TRX1.2 | length 215.2
  Top Layer w0.508: TRX1.2@296.887,49.39 303.237,43.04 303.237,32.626 P466.2@303.237,32.61 ; TRX1.2@299.427,49.39 305.777,43.04 305.777,32.626 P465.2@305.777,32.61 ; TRX1.2@302.5,81.698 P467.2@302.5,88.85 ; TRX1.2@305.04,81.698 P461.2@305.04,88.85 ; TRX1.2@307.58,81.698 P468.2@307.58,88.85 ; P462.2@313.397,32.61 313.397,32.626 313.397,43.056 320.204,49.863 TRX1.2@320.204,55.511 ; P463.2@328.637,32.61 328.637,32.626 328.637,38.992 338.568,48.923 TRX1.2@338.568,52.615 ; P464.2@331.177,32.626 331.177,39.246 341.108,49.177 TRX1.2@341.108,52.615
  DELETEME w0.508: TRX1.2@296.887,49.39 TRX1.2@299.427,49.39 305.04,55.003 ; TRX1.2@302.5,81.698 TRX1.2@305.04,81.698 ; TRX1.2@307.58,81.698 TRX1.2@305.04,81.698 ; TRX1.2@341.108,52.615 TRX1.2@338.568,52.615 337.101,51.148 324.567,51.148 TRX1.2@320.204,55.511 305.548,55.511 305.04,55.003 ; 305.04,55.003 TRX1.2@305.04,81.698
NetP469_2: P469.2 P470.2 TRX2.5 | length 40.1
  Top Layer w0.508: TRX2.5@250.405,48.898 257.001,42.301 257.001,32.86 P469.2@257.001,32.844 ; TRX2.5@252.945,48.898 259.541,42.301 P470.2@259.541,32.86 ; P470.2@259.541,30.828 P470.2@259.541,30.844
  DELETEME w0.508: TRX2.5@250.405,48.898 TRX2.5@252.945,48.898
NetP471_2: P471.2 P472.2 TRX2.6 | length 49.1
  Top Layer w0.508: P471.2@272.241,32.86 272.241,39.083 281.926,48.768 TRX2.6@281.926,52.123 ; P472.2@274.781,32.844 274.781,32.86 274.781,39.083 284.466,48.768 TRX2.6@284.466,52.123
  DELETEME w0.508: TRX2.6@281.926,52.123 TRX2.6@284.466,52.123
NetP473_2: P473.2 P474.2 P475.2 P476.2 P477.2 P478.2 P479.2 P480.2 TRX2.2 | length 257.5
  Top Layer w0.508: TRX2.2@245.325,48.898 251.921,42.301 251.921,32.86 P476.2@251.921,32.844 ; TRX2.2@247.865,48.898 254.461,42.301 254.461,32.86 P477.2@254.461,32.844 ; TRX2.2@250.938,81.206 250.938,84.362 265.124,98.548 266.759,98.548 P479.2@267.064,98.853 ; TRX2.2@253.478,81.206 253.478,84.362 265.124,96.008 266.759,96.008 P478.2@267.064,96.313 ; TRX2.2@256.018,81.206 256.018,84.362 265.124,93.468 266.759,93.468 P480.2@267.064,93.773 ; P475.2@262.081,32.844 262.081,32.86 262.081,44.163 268.642,50.724 TRX2.2@268.642,55.019 ; P473.2@277.321,32.844 277.321,32.86 277.321,39.083 287.006,48.768 TRX2.2@287.006,52.123 ; P474.2@279.861,32.86 279.861,39.083 289.546,48.768 TRX2.2@289.546,52.123
  DELETEME w0.508: TRX2.2@245.325,48.898 TRX2.2@247.865,48.898 247.865,54.063 253.478,59.676 TRX2.2@253.478,81.206 ; TRX2.2@250.938,81.206 TRX2.2@253.478,81.206 ; 251.46,57.658 TRX2.2@268.642,55.019 273.529,50.132 285.015,50.132 TRX2.2@287.006,52.123 TRX2.2@289.546,52.123 ; TRX2.2@256.018,81.206 TRX2.2@253.478,81.206
NetP481_2: P481.2 P482.2 P483.2 P484.2 SW1.Vout | length 39.4
  Top Layer w0.508: SW1.Vout@248.238,171.516 248.238,179.434 P484.2@248.238,179.45 ; SW1.Vout@250.778,171.516 250.778,179.434 P481.2@250.778,179.45 ; SW1.Vout@253.318,171.516 253.318,179.434 P482.2@253.318,179.45 ; SW1.Vout@255.858,171.516 255.858,179.434 P483.2@255.858,179.45
  DELETEME w0.508: SW1.Vout@248.181,171.459 SW1.Vout@250.721,171.459 SW1.Vout@253.261,171.459 SW1.Vout@255.801,171.459
NetP485_2: P485.2 SW1.PG | length 7.9
  Top Layer w0.508: SW1.PG@263.478,171.516 263.478,179.434 P485.2@263.478,179.45
NetP486_2: P486.2 P487.2 P488.2 P489.2 P490.2 P491.2 P492.2 SW1.GND | length 113.9
  Top Layer w0.508: SW1.GND@240.618,171.516 240.618,179.434 P488.2@240.618,179.45 ; SW1.GND@243.101,129.434 243.101,121.83 243.412,121.519 243.412,120.744 P492.2@243.412,120.728 ; SW1.GND@243.158,171.516 243.158,179.434 P487.2@243.158,179.45 ; SW1.GND@245.641,129.434 245.952,129.123 245.952,121.519 245.952,120.744 P491.2@245.952,120.728 ; SW1.GND@245.698,171.516 245.698,179.434 P486.2@245.698,179.45 ; SW1.GND@248.181,129.434 248.492,129.123 248.492,121.519 248.492,120.744 P490.2@248.492,120.728 ; SW1.GND@250.721,129.434 251.032,129.123 251.032,121.519 251.032,120.744 P489.2@251.032,120.728
  DELETEME w0.508: SW1.GND@240.561,171.459 SW1.GND@243.101,171.459 SW1.GND@245.641,171.459 SW1.GND@245.641,129.434 ; SW1.GND@243.101,129.434 SW1.GND@245.641,129.434 ; SW1.GND@250.721,129.434 SW1.GND@248.181,129.434 SW1.GND@245.641,129.434
NetP493_2: P493.2 P494.2 P495.2 P496.2 SW2.Vout | length 38.9
  Top Layer w0.508: SW2.Vout@370.284,124.786 P496.2@370.284,132.612 ; SW2.Vout@372.824,124.786 P495.2@372.824,132.596 ; SW2.Vout@375.364,124.786 P494.2@375.364,132.596 ; SW2.Vout@377.904,124.786 P493.2@377.904,132.612
  DELETEME w0.508: SW2.Vout@370.284,124.786 SW2.Vout@372.824,124.786 SW2.Vout@375.364,124.786 SW2.Vout@377.904,124.786
NetP497_2: P497.2 SW2.PG | length 7.8
  Top Layer w0.508: SW2.PG@385.524,124.786 P497.2@385.524,132.612
NetP498_2: P498.2 P499.2 P500.2 P501.2 P502.2 P503.2 P504.2 SW2.GND | length 110.1
  Top Layer w0.508: SW2.GND@362.664,124.786 P504.2@362.664,132.612 ; P501.2@365.204,74.776 SW2.GND@365.204,82.761 ; SW2.GND@365.204,124.786 P503.2@365.204,132.596 ; P500.2@367.744,74.776 SW2.GND@367.744,82.761 ; SW2.GND@367.744,124.786 P502.2@367.744,132.612 ; P499.2@370.284,74.776 SW2.GND@370.284,82.761 ; P498.2@372.824,74.776 SW2.GND@372.824,82.761
  DELETEME w0.508: SW2.GND@362.664,124.786 SW2.GND@365.204,124.786 SW2.GND@367.744,124.786 SW2.GND@367.744,82.761 ; SW2.GND@365.204,82.761 SW2.GND@367.744,82.761 ; SW2.GND@372.824,82.761 SW2.GND@370.284,82.761 SW2.GND@367.744,82.761
NetU2_11: U2.11 U8.8 | length 3.5
  Top Layer w0.508: U8.8@90.075,158.625 U2.11@90.075,162.125
NetU2_12: U2.12 U8.7 | length 3.5
  Top Layer w0.508: U8.7@91.345,158.625 U2.12@91.345,162.125
NetU2_13: U2.13 U8.6 | length 3.5
  Top Layer w0.508: U8.6@92.615,158.625 U2.13@92.615,162.125
NetU2_14: U2.14 U8.5 | length 3.5
  Top Layer w0.508: U8.5@93.885,158.625 U2.14@93.885,162.125
NetU2_15: U2.15 U8.4 | length 3.5
  Top Layer w0.508: U8.4@95.155,158.625 U2.15@95.155,162.125
NetU2_16: U2.16 U8.3 | length 3.5
  Top Layer w0.508: U8.3@96.425,158.625 U2.16@96.425,162.125
NetU2_17: U2.17 U8.2 | length 3.5
  Top Layer w0.508: U8.2@97.695,158.625 U2.17@97.695,162.125
NetU2_18: U2.18 U8.1 | length 3.5
  Top Layer w0.508: U8.1@98.965,158.625 U2.18@98.965,162.125
NetU3_11: U3.11 U9.8 | length 3.5
  Top Layer w0.508: U9.8@70,158.5 U3.11@70,162
NetU3_12: U3.12 U9.7 | length 3.5
  Top Layer w0.508: U9.7@71.27,158.5 U3.12@71.27,162
NetU3_13: U3.13 U9.6 | length 3.5
  Top Layer w0.508: U9.6@72.54,158.5 U3.13@72.54,162
NetU3_14: U3.14 U9.5 | length 3.5
  Top Layer w0.508: U9.5@73.81,158.5 U3.14@73.81,162
NetU3_15: U3.15 U9.4 | length 3.5
  Top Layer w0.508: U9.4@75.08,158.5 U3.15@75.08,162
NetU3_16: U3.16 U9.3 | length 3.5
  Top Layer w0.508: U9.3@76.35,158.5 U3.16@76.35,162
NetU3_17: U3.17 U9.2 | length 3.5
  Top Layer w0.508: U9.2@77.62,158.5 U3.17@77.62,162
NetU3_18: U3.18 U9.1 | length 3.5
  Top Layer w0.508: U9.1@78.89,158.5 U3.18@78.89,162
NetU4_11: U4.11 U10.8 | length 3.5
  Top Layer w0.152: U4.11@242.25,235 U10.8@245.75,235
NetU4_12: U4.12 U10.7 | length 3.5
  Top Layer w0.152: U4.12@242.25,236.27 U10.7@245.75,236.27
NetU4_13: U4.13 U10.6 | length 3.5
  Top Layer w0.152: U4.13@242.25,237.54 U10.6@245.75,237.54
NetU4_14: U4.14 U10.5 | length 3.5
  Top Layer w0.152: U4.14@242.25,238.81 U10.5@245.75,238.81
NetU4_15: U4.15 U10.4 | length 3.5
  Top Layer w0.152: U4.15@242.25,240.08 U10.4@245.75,240.08
NetU4_16: U4.16 U10.3 | length 3.5
  Top Layer w0.152: U4.16@242.25,241.35 U10.3@245.75,241.35
NetU4_17: U4.17 U10.2 | length 3.5
  Top Layer w0.152: U4.17@242.25,242.62 U10.2@245.75,242.62
NetU4_18: U4.18 U10.1 | length 3.5
  Top Layer w0.152: U4.18@242.25,243.89 U10.1@245.75,243.89
NetU5_11: U5.11 U11.8 | length 3.5
  Top Layer w0.508: U11.8@110.573,158.6 U5.11@110.573,162.1
NetU5_12: U5.12 U11.7 | length 3.5
  Top Layer w0.508: U11.7@111.843,158.6 U5.12@111.843,162.1
NetU5_13: U5.13 U11.6 | length 3.5
  Top Layer w0.508: U11.6@113.113,158.6 U5.13@113.113,162.1
NetU5_14: U5.14 U11.5 | length 3.5
  Top Layer w0.508: U11.5@114.383,158.6 U5.14@114.383,162.1
NetU5_15: U5.15 U11.4 | length 3.5
  Top Layer w0.508: U11.4@115.653,158.6 U5.15@115.653,162.1
NetU5_16: U5.16 U11.3 | length 3.5
  Top Layer w0.508: U11.3@116.923,158.6 U5.16@116.923,162.1
NetU5_17: U5.17 U11.2 | length 3.5
  Top Layer w0.508: U11.2@118.193,158.6 U5.17@118.193,162.1
NetU5_18: U5.18 U11.1 | length 3.5
  Top Layer w0.508: U11.1@119.463,158.6 U5.18@119.463,162.1
NetU6_11: U6.11 U12.8 | length 3.5
  Top Layer w0.152: U12.8@186.75,267.75 U6.11@190.25,267.75
NetU6_12: U6.12 U12.7 | length 3.5
  Top Layer w0.152: U12.7@186.75,266.48 U6.12@190.25,266.48
NetU6_13: U6.13 U12.6 | length 3.5
  Top Layer w0.152: U12.6@186.75,265.21 U6.13@190.25,265.21
NetU6_14: U6.14 U12.5 | length 3.5
  Top Layer w0.152: U12.5@186.75,263.94 U6.14@190.25,263.94
NetU6_15: U6.15 U12.4 | length 3.5
  Top Layer w0.152: U12.4@186.75,262.67 U6.15@190.25,262.67
NetU6_16: U6.16 U12.3 | length 3.5
  Top Layer w0.152: U12.3@186.75,261.4 U6.16@190.25,261.4
NetU6_17: U6.17 U12.2 | length 3.5
  Top Layer w0.152: U12.2@186.75,260.13 U6.17@190.25,260.13
NetU6_18: U6.18 U12.1 | length 3.5
  Top Layer w0.152: U12.1@186.75,258.86 U6.18@190.25,258.86
NetU7_11: U7.11 U13.8 | length 3.5
  Top Layer w0.152: U13.8@194.25,242.75 U7.11@197.75,242.75
NetU7_12: U7.12 U13.7 | length 3.5
  Top Layer w0.152: U13.7@194.25,241.48 U7.12@197.75,241.48
NetU7_13: U7.13 U13.6 | length 3.5
  Top Layer w0.152: U13.6@194.25,240.21 U7.13@197.75,240.21
NetU7_14: U7.14 U13.5 | length 3.5
  Top Layer w0.152: U13.5@194.25,238.94 U7.14@197.75,238.94
NetU7_15: U7.15 U13.4 | length 3.5
  Top Layer w0.152: U13.4@194.25,237.67 U7.15@197.75,237.67
NetU7_16: U7.16 U13.3 | length 3.5
  Top Layer w0.152: U13.3@194.25,236.4 U7.16@197.75,236.4
NetU7_17: U7.17 U13.2 | length 3.5
  Top Layer w0.152: U13.2@194.25,235.13 U7.17@197.75,235.13
NetU7_18: U7.18 U13.1 | length 3.5
  Top Layer w0.152: U13.1@194.25,233.86 U7.18@197.75,233.86
NetU14_11: U14.11 U20.8 | length 3
  Top Layer w0.152: U14.11@376.25,301.75 U20.8@379.25,301.75
NetU14_12: U14.12 U20.7 | length 3
  Top Layer w0.152: U14.12@376.25,303.02 U20.7@379.25,303.02
NetU14_13: U14.13 U20.6 | length 3
  Top Layer w0.152: U14.13@376.25,304.29 U20.6@379.25,304.29
NetU14_14: U14.14 U20.5 | length 3
  Top Layer w0.152: U14.14@376.25,305.56 U20.5@379.25,305.56
NetU14_15: U14.15 U20.4 | length 3
  Top Layer w0.152: U14.15@376.25,306.83 U20.4@379.25,306.83
NetU14_16: U14.16 U20.3 | length 3
  Top Layer w0.152: U14.16@376.25,308.1 U20.3@379.25,308.1
NetU14_17: U14.17 U20.2 | length 3
  Top Layer w0.152: U14.17@376.25,309.37 U20.2@379.25,309.37
NetU14_18: U14.18 U20.1 | length 3
  Top Layer w0.152: U14.18@376.25,310.64 U20.1@379.25,310.64
NetU15_11: U15.11 U21.8 | length 3.3
  Top Layer w0.152: U15.11@376.25,288.25 U21.8@379.5,288.25
NetU15_12: U15.12 U21.7 | length 3.3
  Top Layer w0.152: U15.12@376.25,289.52 U21.7@379.5,289.52
NetU15_13: U15.13 U21.6 | length 3.3
  Top Layer w0.152: U15.13@376.25,290.79 U21.6@379.5,290.79
NetU15_14: U15.14 U21.5 | length 3.3
  Top Layer w0.152: U15.14@376.25,292.06 U21.5@379.5,292.06
NetU15_15: U15.15 U21.4 | length 3.3
  Top Layer w0.152: U15.15@376.25,293.33 U21.4@379.5,293.33
NetU15_16: U15.16 U21.3 | length 3.3
  Top Layer w0.152: U15.16@376.25,294.6 U21.3@379.5,294.6
NetU15_17: U15.17 U21.2 | length 3.3
  Top Layer w0.152: U15.17@376.25,295.87 U21.2@379.5,295.87
NetU15_18: U15.18 U21.1 | length 3.3
  Top Layer w0.152: U15.18@376.25,297.14 U21.1@379.5,297.14
NetU16_11: U16.11 U22.8 | length 3.5
  Top Layer w0.508: U22.8@309.921,209.5 U16.11@313.421,209.5
NetU16_12: U16.12 U22.7 | length 3.5
  Top Layer w0.508: U22.7@309.921,208.23 U16.12@313.421,208.23
NetU16_13: U16.13 U22.6 | length 3.5
  Top Layer w0.508: U22.6@309.921,206.96 U16.13@313.421,206.96
NetU16_14: U16.14 U22.5 | length 3.5
  Top Layer w0.508: U22.5@309.921,205.69 U16.14@313.421,205.69
NetU16_15: U16.15 U22.4 | length 3.5
  Top Layer w0.508: U22.4@309.921,204.42 U16.15@313.421,204.42
NetU16_16: U16.16 U22.3 | length 3.5
  Top Layer w0.508: U22.3@309.921,203.15 U16.16@313.421,203.15
NetU16_17: U16.17 U22.2 | length 3.5
  Top Layer w0.508: U22.2@309.921,201.88 U16.17@313.421,201.88
NetU16_18: U16.18 U22.1 | length 3.5
  Top Layer w0.508: U22.1@309.921,200.61 U16.18@313.421,200.61
NetU17_11: U17.11 U23.8 | length 3.5
  Top Layer w0.508: U23.8@309.921,229.5 U17.11@313.421,229.5
NetU17_12: U17.12 U23.7 | length 3.5
  Top Layer w0.508: U23.7@309.921,228.23 U17.12@313.421,228.23
NetU17_13: U17.13 U23.6 | length 3.5
  Top Layer w0.508: U23.6@309.921,226.96 U17.13@313.421,226.96
NetU17_14: U17.14 U23.5 | length 3.5
  Top Layer w0.508: U23.5@309.921,225.69 U17.14@313.421,225.69
NetU17_15: U17.15 U23.4 | length 3.5
  Top Layer w0.508: U23.4@309.921,224.42 U17.15@313.421,224.42
NetU17_16: U17.16 U23.3 | length 3.5
  Top Layer w0.508: U23.3@309.921,223.15 U17.16@313.421,223.15
NetU17_17: U17.17 U23.2 | length 3.5
  Top Layer w0.508: U23.2@309.921,221.88 U17.17@313.421,221.88
NetU17_18: U17.18 U23.1 | length 3.5
  Top Layer w0.508: U23.1@309.921,220.61 U17.18@313.421,220.61
NetU18_11: U18.11 U24.8 | length 3.5
  Top Layer w0.152: U18.11@155.68,323.25 U24.8@155.68,326.75
NetU18_12: U18.12 U24.7 | length 3.5
  Top Layer w0.152: U18.12@154.41,323.25 U24.7@154.41,326.75
NetU18_13: U18.13 U24.6 | length 3.5
  Top Layer w0.152: U18.13@153.14,323.25 U24.6@153.14,326.75
NetU18_14: U18.14 U24.5 | length 3.5
  Top Layer w0.152: U18.14@151.87,323.25 U24.5@151.87,326.75
NetU18_15: U18.15 U24.4 | length 3.5
  Top Layer w0.152: U18.15@150.6,323.25 U24.4@150.6,326.75
NetU18_16: U18.16 U24.3 | length 3.5
  Top Layer w0.152: U18.16@149.33,323.25 U24.3@149.33,326.75
NetU18_17: U18.17 U24.2 | length 3.5
  Top Layer w0.152: U18.17@148.06,323.25 U24.2@148.06,326.75
NetU18_18: U18.18 U24.1 | length 3.5
  Top Layer w0.152: U18.18@146.79,323.25 U24.1@146.79,326.75
NetU19_11: U19.11 U25.8 | length 3.5
  Top Layer w0.152: U19.11@176.43,323 U25.8@176.43,326.5
NetU19_12: U19.12 U25.7 | length 3.5
  Top Layer w0.152: U19.12@175.16,323 U25.7@175.16,326.5
NetU19_13: U19.13 U25.6 | length 3.5
  Top Layer w0.152: U19.13@173.89,323 U25.6@173.89,326.5
NetU19_14: U19.14 U25.5 | length 3.5
  Top Layer w0.152: U19.14@172.62,323 U25.5@172.62,326.5
NetU19_15: U19.15 U25.4 | length 3.5
  Top Layer w0.152: U19.15@171.35,323 U25.4@171.35,326.5
NetU19_16: U19.16 U25.3 | length 3.5
  Top Layer w0.152: U19.16@170.08,323 U25.3@170.08,326.5
NetU19_17: U19.17 U25.2 | length 3.5
  Top Layer w0.152: U19.17@168.81,323 U25.2@168.81,326.5
NetU19_18: U19.18 U25.1 | length 3.5
  Top Layer w0.152: U19.18@167.54,323 U25.1@167.54,326.5
NewNet1: BCR1.0@212.071,43.032 BCR1.0@212.339,42.032 BCR1.0@212.339,44.032 BCR1.0@213.071,41.3 BCR1.0@213.071,44.764 BCR1.0@214.071,41.032 BCR1.0@214.071,43.032 BCR1.0@214.071,45.032 BCR1.0@215.071,41.3 BCR1.0@215.071,44.764 BCR1.0@215.803,42.032 BCR1.0@215.803,44.032 BCR1.0@216.071,43.032
NewNet2: BCR1.0@49.071,124.032 BCR1.0@49.339,123.032 BCR1.0@49.339,125.032 BCR1.0@50.071,122.3 BCR1.0@50.071,125.764 BCR1.0@51.071,122.032 BCR1.0@51.071,124.032 BCR1.0@51.071,126.032 BCR1.0@52.071,122.3 BCR1.0@52.071,125.764 BCR1.0@52.803,123.032 BCR1.0@52.803,125.032 BCR1.0@53.071,124.032
NewNet3: BCR1.0@212.071,124.032 BCR1.0@212.339,123.032 BCR1.0@212.339,125.032 BCR1.0@213.071,122.3 BCR1.0@213.071,125.764 BCR1.0@214.071,122.032 BCR1.0@214.071,124.032 BCR1.0@214.071,126.032 BCR1.0@215.071,122.3 BCR1.0@215.071,125.764 BCR1.0@215.803,123.032 BCR1.0@215.803,125.032 BCR1.0@216.071,124.032
NewNet4: BCR1.0@41.071,43.032 BCR1.0@41.339,42.032 BCR1.0@41.339,44.032 BCR1.0@42.071,41.3 BCR1.0@42.071,44.764 BCR1.0@43.071,41.032 BCR1.0@43.071,43.032 BCR1.0@43.071,45.032 BCR1.0@44.071,41.3 BCR1.0@44.071,44.764 BCR1.0@44.803,42.032 BCR1.0@44.803,44.032 BCR1.0@45.071,43.032
NewNet5: COMMS1.@259.85,229.937 COMMS1.@260.202,228.625 COMMS1.@260.202,231.249 COMMS1.@261.162,232.211 COMMS1.@261.163,227.664 COMMS1.@262.475,227.312 COMMS1.@262.475,229.937 COMMS1.@262.475,232.562 COMMS1.@263.787,227.664 COMMS1.@263.787,232.21 COMMS1.@264.748,228.625 COMMS1.@264.748,231.25 COMMS1.@265.1,229.937
NewNet6: COMMS1.@179.85,229.937 COMMS1.@180.202,228.625 COMMS1.@180.202,231.249 COMMS1.@181.162,232.211 COMMS1.@181.163,227.664 COMMS1.@182.475,227.312 COMMS1.@182.475,229.937 COMMS1.@182.475,232.562 COMMS1.@183.787,227.664 COMMS1.@183.787,232.21 COMMS1.@184.748,228.625 COMMS1.@184.748,231.25 COMMS1.@185.1,229.937
NewNet7: COMMS1.@259.848,309.924 COMMS1.@260.2,308.612 COMMS1.@260.2,311.236 COMMS1.@261.16,312.198 COMMS1.@261.161,307.651 COMMS1.@262.473,307.299 COMMS1.@262.473,309.924 COMMS1.@262.473,312.549 COMMS1.@263.785,307.651 COMMS1.@263.785,312.197 COMMS1.@264.746,308.612 COMMS1.@264.746,311.237 COMMS1.@265.098,309.924
NewNet8: COMMS1.@179.85,309.937 COMMS1.@180.202,308.625 COMMS1.@180.202,311.249 COMMS1.@181.162,312.211 COMMS1.@181.163,307.664 COMMS1.@182.475,307.312 COMMS1.@182.475,309.937 COMMS1.@182.475,312.562 COMMS1.@183.787,307.664 COMMS1.@183.787,312.21 COMMS1.@184.748,308.625 COMMS1.@184.748,311.25 COMMS1.@185.1,309.937
NewNet9: LDO1.
NewNet10: LDO2.
NewNet11: SW2.@352.059,124.786 SW2.@352.327,123.786 SW2.@352.327,125.786 SW2.@353.059,123.054 SW2.@353.059,126.518 SW2.@354.059,122.786 SW2.@354.059,124.786 SW2.@354.059,126.786 SW2.@355.059,123.054 SW2.@355.059,126.518 SW2.@355.791,123.786 SW2.@355.791,125.786 SW2.@356.059,124.786
NewNet12: SW2.@352.059,82.786 SW2.@352.327,81.786 SW2.@352.327,83.786 SW2.@353.059,81.054 SW2.@353.059,84.518 SW2.@354.059,80.786 SW2.@354.059,82.786 SW2.@354.059,84.786 SW2.@355.059,81.054 SW2.@355.059,84.518 SW2.@355.791,81.786 SW2.@355.791,83.786 SW2.@356.059,82.786
NewNet13: SW2.@394.059,82.786 SW2.@394.327,81.786 SW2.@394.327,83.786 SW2.@395.059,81.054 SW2.@395.059,84.518 SW2.@396.059,80.786 SW2.@396.059,82.786 SW2.@396.059,84.786 SW2.@397.059,81.054 SW2.@397.059,84.518 SW2.@397.791,81.786 SW2.@397.791,83.786 SW2.@398.059,82.786
NewNet14: SW2.@394.059,124.786 SW2.@394.327,123.786 SW2.@394.327,125.786 SW2.@395.059,123.054 SW2.@395.059,126.518 SW2.@396.059,122.786 SW2.@396.059,124.786 SW2.@396.059,126.786 SW2.@397.059,123.054 SW2.@397.059,126.518 SW2.@397.791,123.786 SW2.@397.791,125.786 SW2.@398.059,124.786
NewNet15: TRX1.@336.927,41.499 TRX1.@337.195,40.499 TRX1.@337.195,42.499 TRX1.@337.927,39.767 TRX1.@337.927,43.231 TRX1.@338.927,39.499 TRX1.@338.927,41.499 TRX1.@338.927,43.499 TRX1.@339.927,39.767 TRX1.@339.927,43.231 TRX1.@340.659,40.499 TRX1.@340.659,42.499 TRX1.@340.927,41.499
